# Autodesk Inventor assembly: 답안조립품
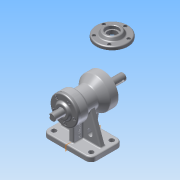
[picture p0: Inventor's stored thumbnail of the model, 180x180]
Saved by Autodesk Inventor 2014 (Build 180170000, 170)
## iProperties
Created: 2015-08
Part Number: 답안조립품
Document SubType Name: Assembly
Designer: study
Author: study
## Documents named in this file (8)
- C:\Users\study\Desktop\450805V1026\답안조립품.iam
- C:\Users\study\Desktop\450805V1026\1-본체.ipt
- C:\Users\study\Desktop\450805V1026\베어링 6203.ipt
- C:\Users\study\Desktop\450805V1026\M4x0.5.ipt
- C:\Users\study\Desktop\450805V1026\뒤커버.ipt
- C:\Users\study\Desktop\450805V1026\축.ipt
- C:\Users\study\Desktop\450805V1026\베어링 6205.ipt
- C:\Users\study\Desktop\450805V1026\앞커버.ipt
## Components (6 placed, 2 different names)
1. 1-본체:1
2. M4x0.5:1
3. M4x0.5:2
4. M4x0.5:3
5. M4x0.5:4
6. M4x0.5:5
